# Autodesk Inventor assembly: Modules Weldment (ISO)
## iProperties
Created: 2007-02
Part Number: Modules Weldment (ISO)
Document SubType Name: Weldment
Designer: Wally Jones
Weld Material: Welded Aluminum-6061
Author: Wally Jones
